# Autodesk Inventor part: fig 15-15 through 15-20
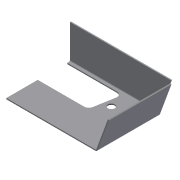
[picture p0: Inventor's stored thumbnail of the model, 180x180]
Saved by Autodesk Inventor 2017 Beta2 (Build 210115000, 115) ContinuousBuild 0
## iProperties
Created: 2005-03
Part Number: fig 15-15 through 15-20
Document SubType Name: Sheet Metal
Designer: CADCIM
Manufacturer: Standard
Standards Organization: Custom
Density: 1 g/cm^3
Sheet Metal Rule: Default
Material: Generic
Flat Pattern Width: 4.32624 cm
Flat Pattern Length: 5.50678 cm
Flat Pattern Area: 23.8236 cm^2
Sheet Metal Width: 43.262 mm
Sheet Metal Length: 55.068 mm
Sheet Metal Area: 2382.364 mm^2
Appearance: Default
Author: CADCIM
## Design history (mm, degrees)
node "Face2"
  sketch "Sketch1" dims "d32" = 0.5 (= BendRadius), "CornerReliefSize" = 2 (= 4 x Thickness)
    geometry: L1 (-36, -8.631)-(4.238, -8.631); L2 (4.238, -8.631)-(4.238, 20); L3 (4.238, 20)-(-36, 20); L4 (-36, 20)-(-36, -8.631)
    constraints: 8 end point, 2 parallel, 1 horizontal, 1 perpendicular
node "Flange3"
node "Flange2"
feature "Corner2" dims "d36" = 2 (= CornerReliefSize), "d37" = 0.5 (= BendRadius), "d38" = 0.5 (= Thickness), "d39" = 0, "Thickness" = 0.5
sketch "Sketch5"
  geometry: 1 further point
sketch "Sketch6"
  geometry: 3 further points
feature "iFeature14:1" sketch "Sketch6" dims "d43" = 3.048 (derived), "d45" = 16.6624 (derived)
body "Solid1"
face "Plate2" dims "d32" = 0.5 (= BendRadius), "Thickness" = 0.5, "CornerReliefSize" = 2 (= 4 x Thickness)
sketch "Sketch3" dims "BendReliefDepth" = 0.25 (= 0.5 x Thickness)
  geometry: L1 through (19.678, 0) direction (1, 0); L2 (39.356, 0)-(39.356, 15); L3 (39.356, 15)-(0, 15); L4 through (0, 7.5) direction (0, -1)
  constraints: 6 end point, 1 horizontal, 1 perpendicular, 1 vertical
face "Plate4" dims "d18" = 0.5 (= BendReliefWidth), "d20" = 1 (= MinimumRemnant), "d22" = 15, "d23" = 90 deg, "d24" = 0.5 (= BendRadius), "d32" = 0.5 (= BendRadius), "Thickness" = 0.5, "BendReliefDepth" = 0.25 (= 0.5 x Thickness), "CornerReliefSize" = 2 (= 4 x Thickness)
bend "Bend2" dims "d18" = 0.5 (= BendReliefWidth), "d19" = 0.25 (= BendReliefDepth), "d20" = 1 (= MinimumRemnant), "d21" = 0.5 (= BendRadius), "d22" = 15, "d23" = 90 deg, "d24" = 0.5 (= BendRadius), "SeamGap" = 0.01, "Thickness" = 0.5
node "FlatPattern"
sketch "Sketch4" dims "d29" = 0.5 (= BendReliefWidth), "d30" = 0.25 (= BendReliefDepth), "d31" = 1 (= MinimumRemnant), "SeamGap" = 0.01
  geometry: L1 through (14.316, 0) direction (1, 0); L2 (28.631, 0)-(28.631, 15); L3 (28.631, 15)-(0, 15); L4 through (0, 7.5) direction (-5.3e-17, -1)
  constraints: 6 end point, 1 horizontal, 1 perpendicular, 1 vertical
face "Plate5" dims "d29" = 0.5 (= BendReliefWidth), "d30" = 0.25 (= BendReliefDepth), "d31" = 1 (= MinimumRemnant), "d32" = 0.5 (= BendRadius), "d33" = 15, "d34" = 70 deg, "d35" = 0.5 (= BendRadius), "SeamGap" = 0.01, "Thickness" = 0.5, "CornerReliefSize" = 2 (= 4 x Thickness)
bend "Bend3" dims "d29" = 0.5 (= BendReliefWidth), "d30" = 0.25 (= BendReliefDepth), "d31" = 1 (= MinimumRemnant), "d32" = 0.5 (= BendRadius), "d33" = 15, "d34" = 70 deg, "d35" = 0.5 (= BendRadius), "SeamGap" = 0.01, "Thickness" = 0.5
feature "FlatPatternExtrusion2" dims "d0" = 0.5 (derived)
other parameters: "BendRadius" = 0.5 (= Thickness), "BendReliefWidth" = 0.5 (= Thickness), "MinimumRemnant" = 1 (= 2 x Thickness), "TransitionRadius" = 0.5 (= BendRadius), "d0" = 0.5 (= BendRadius), "d10" = 0.5 (= BendRadius), "JacobiRadiusSize" = 0.5 (= Thickness), "GapSize" = 0.5 (= Thickness), "d48" = 0
